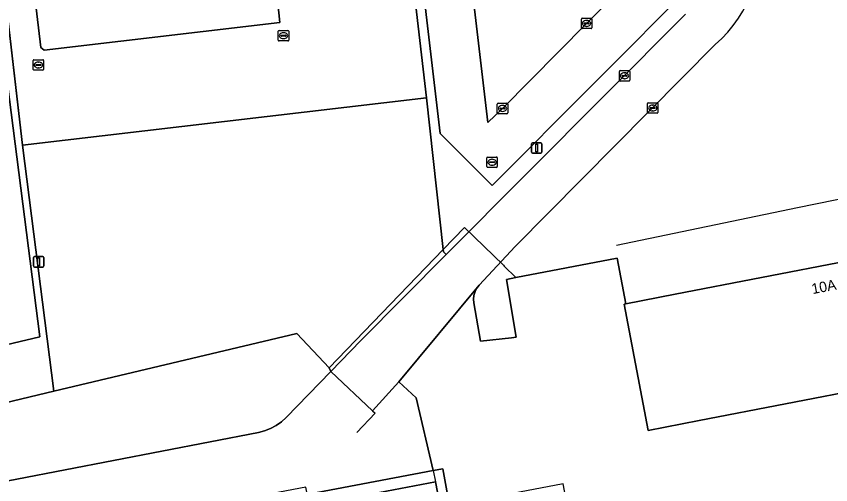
# Model space of a CAD drawing. Extents: x 161477 to 163040, y 383680 to 384871.
# Drawn here: x 161782.1 to 161860.2, y 383906.2 to 383951.2 of the extents above; entities that cross this region are included whole.
import ezdxf

# ---------------------------------------------------------------- set-up
doc = ezdxf.new("R2010")
doc.units = 0
for name, color, linetype in [('IMGEO_Berm_onverhard', 7, 'Continuous'), ('IMGEO_Erf', 7, 'Continuous'), ('IMGEO_Groenvoorziening', 7, 'Continuous'), ('IMGEO_Hek', 7, 'Continuous'), ('IMGEO_Kolk', 7, 'Continuous'), ('IMGEO_Lichtmast', 7, 'Continuous'), ('IMGEO_Overkapping', 7, 'Continuous'), ('IMGEO_Pand', 7, 'Continuous'), ('IMGEO_Pand_nummerreeks', 7, 'Continuous'), ('IMGEO_Parkeervlak_open', 7, 'Continuous'), ('IMGEO_Rijbaan_lokaal_open', 7, 'Continuous'), ('IMGEO_Rioolput', 7, 'Continuous'), ('IMGEO_Terreindeel_open', 7, 'Continuous')]:
    doc.layers.add(name, color=color, linetype=linetype)

msp = doc.modelspace()

# ---------------------------------------------------------------- linework, layer by layer
at = {"layer": 'IMGEO_Berm_onverhard'}
msp.add_lwpolyline([(161812.061, 383917.437), (161812.228, 383917.078), (161815.107, 383920.055), (161823.305, 383928.305), (161823.043, 383928.556), (161823.018, 383928.784)], close=True, dxfattribs=at)
at = {"layer": 'IMGEO_Erf'}
for points in [[(161815.61, 383993.149), (161789.352, 383990.026), (161784.255, 383989.42), (161776.903, 383988.545), (161782.69, 383938.808), (161821.416, 383943.334)], [(161803.384, 383981.593), (161803.738, 383981.304), (161807.24, 383951.488), (161807.35, 383950.547), (161784.759, 383947.894), (161784.419, 383948.159), (161783.095, 383959.489), (161783.353, 383959.837), (161793.982, 383961.102), (161791.758, 383979.909), (161792.036, 383980.261)]]:
    msp.add_lwpolyline(points, close=True, dxfattribs=at)
msp.add_lwpolyline([(161880.65, 383918.771), (161847.558, 383912.364), (161842.649, 383911.413), (161840.343, 383923.539), (161840.505, 383923.57), (161839.686, 383927.949), (161829.966, 383926.087), (161829.077, 383925.917), (161830.001, 383920.378), (161829.558, 383920.304), (161826.582, 383919.982), (161825.948, 383923.652), (161825.918, 383924.012), (161825.956, 383924.38), (161826.063, 383924.738), (161826.232, 383925.068), (161826.453, 383925.353), (161818.745, 383916.08), (161820.429, 383914.56), (161822.033, 383907.564), (161822.959, 383907.739), (161823.625, 383904.229)], dxfattribs=at)
at = {"layer": 'IMGEO_Groenvoorziening'}
for points in [[(161840.758, 383979.3), (161844.222, 383979.717), (161847.193, 383954.527), (161827.71, 383934.907), (161822.723, 383939.897), (161817.233, 383986.718), (161821.039, 383987.146), (161816.483, 383993.253), (161815.61, 383993.149), (161821.416, 383943.334), (161823.018, 383928.784), (161823.043, 383928.556), (161823.305, 383928.305), (161846.234, 383951.346)], [(161736.627, 383904.51), (161745.122, 383906.315), (161760.825, 383909.682), (161774.226, 383912.484), (161773.612, 383915.18), (161776.37, 383915.808), (161776.984, 383913.112), (161785.682, 383915.185), (161782.69, 383938.808), (161776.903, 383988.545), (161773.511, 383988.142), (161773.581, 383986.311), (161774.344, 383965.696), (161778.462, 383966.235), (161784.326, 383920.396), (161779.862, 383919.357), (161773.251, 383917.914)], [(161849.094, 383948.445), (161829.918, 383929.086), (161826.453, 383925.353), (161826.232, 383925.068), (161826.063, 383924.738), (161825.956, 383924.38), (161825.918, 383924.012), (161825.948, 383923.652), (161826.582, 383919.982), (161829.558, 383920.304), (161830.001, 383920.378), (161829.077, 383925.917), (161829.966, 383926.087), (161839.686, 383927.949), (161840.505, 383923.57), (161845.252, 383924.49), (161878.344, 383930.897)], [(161768.191, 383904.054), (161805.301, 383911.22), (161805.888, 383911.371), (161806.459, 383911.595), (161807, 383911.888), (161807.5, 383912.244), (161807.947, 383912.653), (161812.228, 383917.078), (161812.061, 383917.437), (161808.968, 383920.735), (161785.682, 383915.185), (161776.984, 383913.112), (161774.226, 383912.484), (161760.825, 383909.682), (161745.122, 383906.315), (161736.627, 383904.51)]]:
    msp.add_lwpolyline(points, dxfattribs=at)
msp.add_lwpolyline([(161812.061, 383917.437), (161823.018, 383928.784), (161821.416, 383943.334), (161782.69, 383938.808), (161785.682, 383915.185), (161808.968, 383920.735)], close=True, dxfattribs=at)
msp.add_arc((161839.999, 383958.638), 13.661, 311.74132, 7.6264, dxfattribs=at)
at = {"layer": 'IMGEO_Hek'}
for points in [[(161821.416, 383943.334), (161815.642, 383992.876)], [(161776.926, 383988.348), (161782.69, 383938.808)], [(161782.69, 383938.808), (161821.416, 383943.334)], [(161856.984, 383932.82), (161876.595, 383936.812)], [(161839.61, 383929.205), (161856.984, 383932.82)], [(161812.061, 383917.437), (161823.018, 383928.784), (161825.047, 383930.886)], [(161825.047, 383930.886), (161828.776, 383927.265)], [(161828.776, 383927.265), (161828.861, 383927.181)], [(161829.966, 383926.087), (161839.686, 383927.949)], [(161839.686, 383927.949), (161840.512, 383923.532)], [(161828.861, 383927.181), (161829.966, 383926.087)], [(161808.968, 383920.735), (161785.682, 383915.185)], [(161808.968, 383920.735), (161812.061, 383917.437)], [(161812.061, 383917.437), (161812.228, 383917.078), (161816.239, 383913.303), (161818.745, 383916.08), (161820.429, 383914.56), (161822.033, 383907.564), (161822.28, 383906.491)], [(161785.682, 383915.185), (161776.984, 383913.112), (161774.226, 383912.484)], [(161816.239, 383913.303), (161816.472, 383913.084), (161814.731, 383911.234)]]:
    msp.add_lwpolyline(points, dxfattribs=at)
at = {"layer": 'IMGEO_Kolk'}
for p, q in [((161836.254, 383950.045), (161836.254, 383950.897)), ((161836.329, 383950.971), (161837.181, 383950.971)), ((161836.742, 383950.751), (161836.767, 383950.751)), ((161837.255, 383950.897), (161837.255, 383950.045)), ((161837.181, 383949.971), (161836.329, 383949.971)), ((161836.513, 383950.465), (161836.513, 383950.477)), ((161836.951, 383950.428), (161836.553, 383950.428)), ((161836.556, 383950.514), (161836.954, 383950.514)), ((161836.765, 383950.191), (161836.74, 383950.191)), ((161836.997, 383950.477), (161836.997, 383950.465)), ((161807.196, 383948.868), (161807.196, 383949.72)), ((161807.271, 383949.794), (161808.123, 383949.794)), ((161807.455, 383949.288), (161807.455, 383949.3)), ((161807.893, 383949.251), (161807.495, 383949.251)), ((161807.498, 383949.337), (161807.896, 383949.337)), ((161807.684, 383949.574), (161807.709, 383949.574)), ((161807.939, 383949.3), (161807.939, 383949.288)), ((161808.197, 383949.72), (161808.197, 383948.868)), ((161808.123, 383948.794), (161807.271, 383948.794)), ((161807.707, 383949.014), (161807.682, 383949.014)), ((161783.696, 383946.064), (161783.696, 383946.916)), ((161783.771, 383946.99), (161784.623, 383946.99)), ((161784.184, 383946.77), (161784.209, 383946.77)), ((161784.697, 383946.916), (161784.697, 383946.064)), ((161784.623, 383945.99), (161783.771, 383945.99)), ((161783.955, 383946.484), (161783.955, 383946.496)), ((161784.393, 383946.447), (161783.995, 383946.447)), ((161783.998, 383946.533), (161784.396, 383946.533)), ((161784.207, 383946.21), (161784.182, 383946.21)), ((161784.439, 383946.496), (161784.439, 383946.484)), ((161839.895, 383945.022), (161839.895, 383945.874)), ((161839.97, 383945.948), (161840.822, 383945.948)), ((161840.154, 383945.442), (161840.154, 383945.454)), ((161840.592, 383945.405), (161840.194, 383945.405)), ((161840.197, 383945.491), (161840.595, 383945.491)), ((161840.383, 383945.728), (161840.408, 383945.728)), ((161840.638, 383945.454), (161840.638, 383945.442)), ((161840.896, 383945.874), (161840.896, 383945.022)), ((161840.822, 383944.948), (161839.97, 383944.948)), ((161840.406, 383945.168), (161840.381, 383945.168)), ((161842.67, 383942.865), (161843.522, 383942.865)), ((161828.193, 383941.888), (161828.193, 383942.74)), ((161828.268, 383942.814), (161829.12, 383942.814)), ((161828.452, 383942.308), (161828.452, 383942.32)), ((161828.89, 383942.271), (161828.492, 383942.271)), ((161828.495, 383942.357), (161828.893, 383942.357)), ((161828.681, 383942.594), (161828.706, 383942.594)), ((161828.936, 383942.32), (161828.936, 383942.308)), ((161829.194, 383942.74), (161829.194, 383941.888)), ((161842.595, 383941.939), (161842.595, 383942.791)), ((161842.854, 383942.359), (161842.854, 383942.371)), ((161843.292, 383942.322), (161842.894, 383942.322)), ((161842.897, 383942.408), (161843.295, 383942.408)), ((161843.106, 383942.085), (161843.081, 383942.085)), ((161843.083, 383942.645), (161843.108, 383942.645)), ((161843.338, 383942.371), (161843.338, 383942.359)), ((161843.596, 383942.791), (161843.596, 383941.939)), ((161829.12, 383941.814), (161828.268, 383941.814)), ((161828.704, 383942.034), (161828.679, 383942.034)), ((161843.522, 383941.865), (161842.67, 383941.865))]:
    msp.add_line(p, q, dxfattribs=at)
for points in [[(161836.254, 383950.045), (161836.254, 383950.897)], [(161836.329, 383950.971), (161837.181, 383950.971)], [(161837.255, 383950.897), (161837.255, 383950.045)], [(161837.181, 383949.971), (161836.329, 383949.971)], [(161807.196, 383948.868), (161807.196, 383949.72)], [(161807.271, 383949.794), (161808.123, 383949.794)], [(161808.197, 383949.72), (161808.197, 383948.868)], [(161808.123, 383948.794), (161807.271, 383948.794)], [(161783.696, 383946.064), (161783.696, 383946.916)], [(161783.771, 383946.99), (161784.623, 383946.99)], [(161784.697, 383946.916), (161784.697, 383946.064)], [(161784.623, 383945.99), (161783.771, 383945.99)], [(161839.895, 383945.022), (161839.895, 383945.874)], [(161839.97, 383945.948), (161840.822, 383945.948)], [(161840.896, 383945.874), (161840.896, 383945.022)], [(161840.822, 383944.948), (161839.97, 383944.948)], [(161842.67, 383942.865), (161843.522, 383942.865)], [(161828.193, 383941.888), (161828.193, 383942.74)], [(161828.268, 383942.814), (161829.12, 383942.814)], [(161829.194, 383942.74), (161829.194, 383941.888)], [(161842.595, 383941.939), (161842.595, 383942.791)], [(161843.596, 383942.791), (161843.596, 383941.939)], [(161829.12, 383941.814), (161828.268, 383941.814)], [(161843.522, 383941.865), (161842.67, 383941.865)]]:
    msp.add_lwpolyline(points, dxfattribs=at)
for centre, radius, start, end in [((161836.331, 383950.895), 0.0765, 91.55205, 178.44795), ((161836.331, 383950.895), 0.0765, 91.55205, 178.44795), ((161837.179, 383950.895), 0.0765, 1.55205, 88.44795), ((161837.179, 383950.895), 0.0765, 1.55205, 88.44795), ((161836.331, 383950.047), 0.0765, 181.55205, 268.44795), ((161836.331, 383950.047), 0.0765, 181.55205, 268.44795), ((161836.553, 383950.474), 0.0403, 85.87752, 175.75265), ((161836.55, 383950.464), 0.0366, 178.93798, 274.71019), ((161836.954, 383950.471), 0.043, 264.86636, 352.45326), ((161836.958, 383950.476), 0.0386, 1.73085, 96.63898), ((161837.179, 383950.047), 0.0765, 271.55205, 358.44795), ((161837.179, 383950.047), 0.0765, 271.55205, 358.44795), ((161807.273, 383949.718), 0.0765, 91.55205, 178.44795), ((161807.273, 383949.718), 0.0765, 91.55205, 178.44795), ((161807.495, 383949.297), 0.0403, 85.87752, 175.75265), ((161807.492, 383949.287), 0.0366, 178.93798, 274.71019), ((161807.896, 383949.294), 0.043, 264.86636, 352.45326), ((161807.9, 383949.299), 0.0386, 1.73085, 96.63898), ((161808.121, 383949.718), 0.0765, 1.55205, 88.44795), ((161808.121, 383949.718), 0.0765, 1.55205, 88.44795), ((161807.273, 383948.87), 0.0765, 181.55205, 268.44795), ((161807.273, 383948.87), 0.0765, 181.55205, 268.44795), ((161808.121, 383948.87), 0.0765, 271.55205, 358.44795), ((161808.121, 383948.87), 0.0765, 271.55205, 358.44795), ((161783.773, 383946.914), 0.0765, 91.55205, 178.44795), ((161783.773, 383946.914), 0.0765, 91.55205, 178.44795), ((161784.621, 383946.914), 0.0765, 1.55205, 88.44795), ((161784.621, 383946.914), 0.0765, 1.55205, 88.44795), ((161783.773, 383946.066), 0.0765, 181.55205, 268.44795), ((161783.773, 383946.066), 0.0765, 181.55205, 268.44795), ((161783.995, 383946.493), 0.0403, 85.87752, 175.75265), ((161783.992, 383946.483), 0.0366, 178.93798, 274.71019), ((161784.396, 383946.49), 0.043, 264.86636, 352.45326), ((161784.4, 383946.495), 0.0386, 1.73085, 96.63898), ((161784.621, 383946.066), 0.0765, 271.55205, 358.44795), ((161784.621, 383946.066), 0.0765, 271.55205, 358.44795), ((161839.972, 383945.872), 0.0765, 91.55205, 178.44795), ((161839.972, 383945.872), 0.0765, 91.55205, 178.44795), ((161840.194, 383945.451), 0.0403, 85.87752, 175.75265), ((161840.191, 383945.441), 0.0366, 178.93798, 274.71019), ((161840.595, 383945.448), 0.043, 264.86636, 352.45326), ((161840.599, 383945.453), 0.0386, 1.73085, 96.63898), ((161840.82, 383945.872), 0.0765, 1.55205, 88.44795), ((161840.82, 383945.872), 0.0765, 1.55205, 88.44795), ((161839.972, 383945.024), 0.0765, 181.55205, 268.44795), ((161839.972, 383945.024), 0.0765, 181.55205, 268.44795), ((161840.82, 383945.024), 0.0765, 271.55205, 358.44795), ((161840.82, 383945.024), 0.0765, 271.55205, 358.44795), ((161842.672, 383942.789), 0.0765, 91.55205, 178.44795), ((161842.672, 383942.789), 0.0765, 91.55205, 178.44795), ((161843.52, 383942.789), 0.0765, 1.55205, 88.44795), ((161843.52, 383942.789), 0.0765, 1.55205, 88.44795), ((161828.27, 383942.738), 0.0765, 91.55205, 178.44795), ((161828.27, 383942.738), 0.0765, 91.55205, 178.44795), ((161828.492, 383942.317), 0.0403, 85.87752, 175.75265), ((161828.489, 383942.307), 0.0366, 178.93798, 274.71019), ((161828.893, 383942.314), 0.043, 264.86636, 352.45326), ((161828.897, 383942.319), 0.0386, 1.73085, 96.63898), ((161829.118, 383942.738), 0.0765, 1.55205, 88.44795), ((161829.118, 383942.738), 0.0765, 1.55205, 88.44795), ((161842.894, 383942.368), 0.0403, 85.87752, 175.75265), ((161842.891, 383942.358), 0.0366, 178.93798, 274.71019), ((161843.295, 383942.365), 0.043, 264.86636, 352.45326), ((161843.299, 383942.37), 0.0386, 1.73085, 96.63898), ((161828.27, 383941.89), 0.0765, 181.55205, 268.44795), ((161828.27, 383941.89), 0.0765, 181.55205, 268.44795), ((161829.118, 383941.89), 0.0765, 271.55205, 358.44795), ((161829.118, 383941.89), 0.0765, 271.55205, 358.44795), ((161842.672, 383941.941), 0.0765, 181.55205, 268.44795), ((161842.672, 383941.941), 0.0765, 181.55205, 268.44795), ((161843.52, 383941.941), 0.0765, 271.55205, 358.44795), ((161843.52, 383941.941), 0.0765, 271.55205, 358.44795)]:
    msp.add_arc(centre, radius, start, end, dxfattribs=at)
for centre, major_axis, ratio, start_param, end_param in [((161836.741, 383950.471), (-0.387, 0.002), 0.722429, 4.712389, 7.853982), ((161836.766, 383950.471), (-0.39, 0.002), 0.717154, 1.570796, 4.712389), ((161807.683, 383949.294), (-0.387, 0.002), 0.722429, 4.712389, 7.853982), ((161807.708, 383949.294), (-0.39, 0.002), 0.717154, 1.570796, 4.712389), ((161784.183, 383946.49), (-0.387, 0.002), 0.722429, 4.712389, 7.853982), ((161784.208, 383946.49), (-0.39, 0.002), 0.717154, 1.570796, 4.712389), ((161840.382, 383945.448), (-0.387, 0.002), 0.722429, 4.712389, 7.853982), ((161840.407, 383945.448), (-0.39, 0.002), 0.717154, 1.570796, 4.712389), ((161828.68, 383942.314), (-0.387, 0.002), 0.722429, 4.712389, 7.853982), ((161828.705, 383942.314), (-0.39, 0.002), 0.717154, 1.570796, 4.712389), ((161843.082, 383942.365), (-0.387, 0.002), 0.722429, 4.712389, 7.853982), ((161843.107, 383942.365), (-0.39, 0.002), 0.717154, 1.570796, 4.712389)]:
    msp.add_ellipse(centre, major_axis=major_axis, ratio=ratio, start_param=start_param, end_param=end_param, dxfattribs=at)
at = {"layer": 'IMGEO_Lichtmast'}
for p, q in [((161831.573, 383939.023), (161832.363, 383939.023)), ((161832.363, 383939.023), (161831.573, 383939.023)), ((161831.473, 383938.123), (161831.473, 383938.923)), ((161831.473, 383938.923), (161831.473, 383938.123)), ((161832.463, 383938.923), (161832.463, 383938.123)), ((161832.463, 383938.123), (161832.463, 383938.923)), ((161832.363, 383938.023), (161831.573, 383938.023)), ((161831.573, 383938.023), (161832.363, 383938.023)), ((161783.733, 383927.202), (161783.733, 383928.002)), ((161783.733, 383928.002), (161783.733, 383927.202)), ((161783.833, 383928.102), (161784.623, 383928.102)), ((161784.623, 383928.102), (161783.833, 383928.102)), ((161784.723, 383928.002), (161784.723, 383927.202)), ((161784.723, 383927.202), (161784.723, 383928.002)), ((161784.623, 383927.102), (161783.833, 383927.102)), ((161783.833, 383927.102), (161784.623, 383927.102))]:
    msp.add_line(p, q, dxfattribs=at)
for points in [[(161831.893, 383938.898), (161832.043, 383938.898), (161832.043, 383938.148), (161831.893, 383938.148), (161831.893, 383938.898)], [(161784.153, 383927.977), (161784.303, 383927.977), (161784.303, 383927.227), (161784.153, 383927.227), (161784.153, 383927.977)]]:
    msp.add_lwpolyline(points, dxfattribs=at)
for centre, start, end in [((161831.573, 383938.923), 90, 180), ((161831.573, 383938.923), 90, 180), ((161832.363, 383938.923), 0, 90), ((161832.363, 383938.923), 360, 90), ((161831.573, 383938.123), 180, 270), ((161831.573, 383938.123), 180, 270), ((161832.363, 383938.123), 270, 0), ((161832.363, 383938.123), 270, 0), ((161783.833, 383928.002), 90, 180), ((161783.833, 383928.002), 90, 180), ((161784.623, 383928.002), 0, 90), ((161784.623, 383928.002), 360, 90), ((161783.833, 383927.202), 180, 270), ((161783.833, 383927.202), 180, 270), ((161784.623, 383927.202), 270, 0), ((161784.623, 383927.202), 270, 0)]:
    msp.add_arc(centre, 0.1, start, end, dxfattribs=at)
at = {"layer": 'IMGEO_Overkapping'}
msp.add_lwpolyline([(161835.591, 383900.597), (161834.509, 383906.295), (161823.625, 383904.229), (161824.707, 383898.531), (161827.069, 383898.979)], close=True, dxfattribs=at)
at = {"layer": 'IMGEO_Pand'}
for points in [[(161803.738, 383981.304), (161803.384, 383981.593), (161792.036, 383980.261), (161791.758, 383979.909), (161793.982, 383961.102), (161783.353, 383959.837), (161783.095, 383959.489), (161784.419, 383948.159), (161784.759, 383947.894), (161807.35, 383950.547), (161807.24, 383951.488)], [(161878.358, 383930.822), (161878.344, 383930.897), (161845.252, 383924.49), (161840.505, 383923.57), (161840.343, 383923.539), (161842.649, 383911.413), (161847.558, 383912.364), (161880.65, 383918.771)], [(161804.125, 383904.891), (161784.496, 383901.165), (161786.276, 383891.788), (161823.722, 383898.897), (161822.28, 383906.491), (161810.184, 383904.195), (161809.846, 383905.977)]]:
    msp.add_lwpolyline(points, close=True, dxfattribs=at)
at = {"layer": 'IMGEO_Parkeervlak_open'}
for points in [[(161839.633, 383980.183), (161839.98, 383976.737), (161841.177, 383966.787), (161842.351, 383956.938), (161842.449, 383956.165), (161836.754, 383950.471), (161828.693, 383942.315), (161827.281, 383940.955), (161821.817, 383987.472)], [(161821.21, 383987.165), (161821.039, 383987.146), (161817.233, 383986.718), (161822.723, 383939.897), (161827.71, 383934.907), (161847.193, 383954.527), (161844.222, 383979.717), (161840.758, 383979.3)]]:
    msp.add_lwpolyline(points, dxfattribs=at)
msp.add_lwpolyline([(161774.344, 383965.696), (161773.994, 383965.636), (161779.862, 383919.357), (161784.326, 383920.396), (161778.462, 383966.235)], close=True, dxfattribs=at)
at = {"layer": 'IMGEO_Rijbaan_lokaal_open'}
for points in [[(161821.817, 383987.472), (161827.281, 383940.955), (161828.693, 383942.315), (161836.754, 383950.471), (161842.449, 383956.165), (161842.351, 383956.938), (161841.177, 383966.787), (161839.98, 383976.737), (161839.633, 383980.183)], [(161846.234, 383951.346), (161823.305, 383928.305), (161815.107, 383920.055), (161812.228, 383917.078), (161816.239, 383913.303), (161818.745, 383916.08), (161826.453, 383925.353), (161829.918, 383929.086), (161849.094, 383948.445)], [(161810.912, 383905.453), (161822.033, 383907.564), (161820.429, 383914.56), (161818.745, 383916.08), (161816.239, 383913.303), (161812.228, 383917.078), (161807.947, 383912.653), (161807.5, 383912.244), (161807, 383911.888), (161806.459, 383911.595), (161805.888, 383911.371), (161805.301, 383911.22), (161768.191, 383904.054)]]:
    msp.add_lwpolyline(points, dxfattribs=at)
msp.add_arc((161839.999, 383958.638), 13.661, 311.74132, 7.6264, dxfattribs=at)
at = {"layer": 'IMGEO_Rioolput'}
for p, q in [((161827.188, 383936.731), (161827.188, 383937.583)), ((161827.263, 383937.657), (161828.115, 383937.657)), ((161827.676, 383937.437), (161827.701, 383937.437)), ((161828.189, 383937.583), (161828.189, 383936.731)), ((161828.115, 383936.657), (161827.263, 383936.657)), ((161827.447, 383937.151), (161827.447, 383937.163)), ((161827.885, 383937.114), (161827.487, 383937.114)), ((161827.49, 383937.2), (161827.888, 383937.2)), ((161827.699, 383936.877), (161827.674, 383936.877)), ((161827.931, 383937.163), (161827.931, 383937.151))]:
    msp.add_line(p, q, dxfattribs=at)
for points in [[(161827.188, 383936.731), (161827.188, 383937.583)], [(161827.263, 383937.657), (161828.115, 383937.657)], [(161828.189, 383937.583), (161828.189, 383936.731)], [(161828.115, 383936.657), (161827.263, 383936.657)]]:
    msp.add_lwpolyline(points, dxfattribs=at)
for centre, radius, start, end in [((161827.265, 383937.581), 0.0765, 91.55205, 178.44795), ((161827.265, 383937.581), 0.0765, 91.55205, 178.44795), ((161828.113, 383937.581), 0.0765, 1.55205, 88.44795), ((161828.113, 383937.581), 0.0765, 1.55205, 88.44795), ((161827.265, 383936.733), 0.0765, 181.55205, 268.44795), ((161827.265, 383936.733), 0.0765, 181.55205, 268.44795), ((161827.487, 383937.16), 0.0403, 85.87752, 175.75265), ((161827.484, 383937.15), 0.0366, 178.93798, 274.71019), ((161827.888, 383937.157), 0.043, 264.86636, 352.45326), ((161827.892, 383937.162), 0.0386, 1.73085, 96.63898), ((161828.113, 383936.733), 0.0765, 271.55205, 358.44795), ((161828.113, 383936.733), 0.0765, 271.55205, 358.44795)]:
    msp.add_arc(centre, radius, start, end, dxfattribs=at)
for centre, major_axis, ratio, start_param, end_param in [((161827.675, 383937.157), (-0.387, 0.002), 0.722429, 4.712389, 7.853982), ((161827.7, 383937.157), (-0.39, 0.002), 0.717154, 1.570796, 4.712389)]:
    msp.add_ellipse(centre, major_axis=major_axis, ratio=ratio, start_param=start_param, end_param=end_param, dxfattribs=at)
at = {"layer": 'IMGEO_Terreindeel_open'}
for points in [[(161823.625, 383904.229), (161822.959, 383907.739), (161822.033, 383907.564), (161810.912, 383905.453)], [(161810.184, 383904.195), (161822.28, 383906.491), (161823.722, 383898.897)]]:
    msp.add_lwpolyline(points, dxfattribs=at)

# ---------------------------------------------------------------- texts
at = {"layer": 'IMGEO_Pand_nummerreeks'}
msp.add_text('10A', height=1, rotation=10.76015, dxfattribs=at).set_placement((161858.42, 383924.498))

doc.saveas('drawing.dxf')
